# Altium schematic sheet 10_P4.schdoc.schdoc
size 309 x 223 mm; Symbol: A4_Schematic_0605; Device: A4_Schematic_0605; @Project Name: MDIO-Board_Rev_01(0124); @Page Count: 10; @Update Date: 2024-05-24; @Create Date: 2024-05-19; @Schematic Name: Schematic1; @Page No: 4; @Page Name: P4
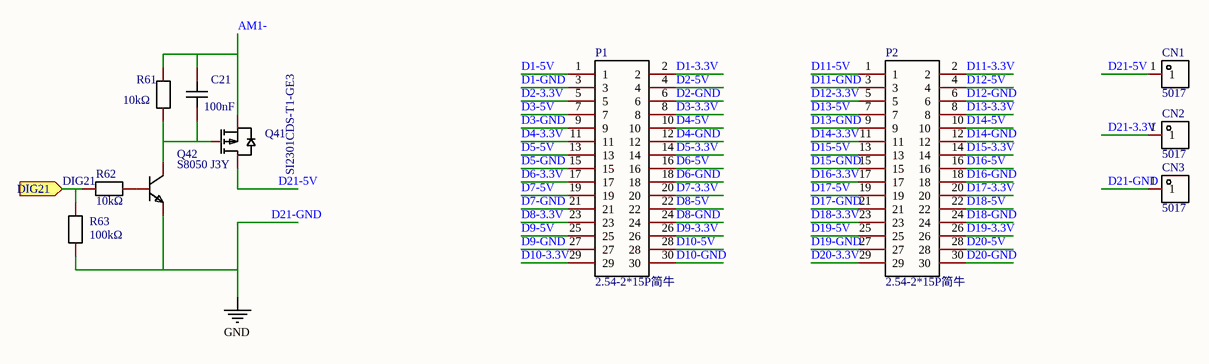
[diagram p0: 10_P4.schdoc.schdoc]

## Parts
C21  100nF  [C0603]
CN1  5017  [CONN-SMD_5017]
CN2  5017  [CONN-SMD_5017]
CN3  5017  [CONN-SMD_5017]
P1  2.54-2*15P简牛  [IDC-TH_30P-P2.54-V-R2-C15-S2.54]
P2  2.54-2*15P简牛  [IDC-TH_30P-P2.54-V-R2-C15-S2.54]
Q41  SI2301CDS-T1-GE3  [SOT-23-3_L3.0-W1.7-P0.95-LS2.9-BR]
Q42  S8050 J3Y  [SOT-23-3_L3.0-W1.7-P0.95-LS2.9-BR]
R61  10kΩ  [R0603]
R62  10kΩ  [R0603]
R63  100kΩ  [R0603]

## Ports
DIG21 (in)

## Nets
D21-GND: CN3.1 Q42.2(E) R63.1  [also labelled GND]
AM1-: C21.1 Q41.2(S) R61.2
D1-3.3V: P1.2
D1-5V: P1.1
D1-GND: P1.3
D2-3.3V: P1.5
D2-5V: P1.4
D2-GND: P1.6
D3-3.3V: P1.8
D3-5V: P1.7
D3-GND: P1.9
D4-3.3V: P1.11
D4-5V: P1.10
D4-GND: P1.12
D5-3.3V: P1.14
D5-5V: P1.13
D5-GND: P1.15
D6-3.3V: P1.17
D6-5V: P1.16
D6-GND: P1.18
D7-3.3V: P1.20
D7-5V: P1.19
D7-GND: P1.21
D8-3.3V: P1.23
D8-5V: P1.22
D8-GND: P1.24
D9-3.3V: P1.26
D9-5V: P1.25
D9-GND: P1.27
D10-3.3V: P1.29
D10-5V: P1.28
D10-GND: P1.30
D11-3.3V: P2.2
D11-5V: P2.1
D11-GND: P2.3
D12-3.3V: P2.5
D12-5V: P2.4
D12-GND: P2.6
D13-3.3V: P2.8
D13-5V: P2.7
D13-GND: P2.9
D14-3.3V: P2.11
D14-5V: P2.10
D14-GND: P2.12
D15-3.3V: P2.14
D15-5V: P2.13
D15-GND: P2.15
D16-3.3V: P2.17
D16-5V: P2.16
D16-GND: P2.18
D17-3.3V: P2.20
D17-5V: P2.19
D17-GND: P2.21
D18-3.3V: P2.23
D18-5V: P2.22
D18-GND: P2.24
D19-3.3V: P2.26
D19-5V: P2.25
D19-GND: P2.27
D20-3.3V: P2.29
D20-5V: P2.28
D20-GND: P2.30
D21-3.3V: CN2.1
D21-5V: CN1.1 Q41.3(D)
DIG21: R62.2 R63.2 ; port DIG21
NetC21_2: C21.2 Q41.1(G) Q42.3(C) R61.1
NetQ42_1: Q42.1(B) R62.1

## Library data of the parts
C21 = CC0603KRX7R9BB104: Manufacturer: YAGEO(国巨); Add into BOM: yes; Tolerance: ±10%; Description: Capacitance: Tolerance:±10% Tolerance:±10% Voltage Rated: Temperature Coefficient:
CN1-CN3 = 5017: Symbol: 5017_C9900015874; Add into BOM: yes
P1 P2 = 2.54-2*15P简牛: Manufacturer: BOOMELE(博穆精密); Symbol: 2X15P; Add into BOM: yes; Connector Type: 简牛座; Pitch: 2.54mm; Holder Type: Straight; Pin Number in each Row: 15; Description: Connector Type:简牛座 Pitch:2.54mm Structure:2x15P Holder Type:Straight Row Spacing:2.54mm Number of Rows:2 Pin Number in each Row:15 Contact Material:- Contact Plating:-
Q41 = SI2301CDS-T1-GE3: Manufacturer: VISHAY(威世); Add into BOM: yes; Type: 1个PChannel; Power Dissipation (Pd): ；; Drain Source On Resistance (RDS(on)@Vgs,Id): 112mΩ@4.5V,2.8A; Gate Threshold Voltage (Vgs(th)@Id): 1V@250uA; Total Gate Charge (Qg@Vgs): 10nC@4.5V; Input Capacitance (Ciss@Vds): 405pF@10V; Description: Type:1个PChannel Drain Source Voltage (Vdss): Continuous Drain Current (Id): Power Dissipation (Pd):； Drain Source On Resistance (RDS(on)@Vgs,Id):112mΩ@4.5V,2.8A Gate Threshold Voltage (Vgs(th)@Id):1V@250uA Total Gate Charge (Qg@Vgs):10nC@4.5V Input Capaci
Q42 = S8050 J3Y_C2146: Manufacturer: CJ(江苏长电/长晶); Symbol: S8050_C2146; Add into BOM: yes; DC Current Gain (hFE@Ic,Vce): 200@50mA,1V; Transition Frequency (fT): 150MHz; Collector Cut-Off Current (Icbo): 100nA; Collector-Emitter Saturation Voltage (VCE(sat)@Ic,Ib): 600mV@500mA,50mA; Description: Transistor Type: Collector Current (Ic): Collector-Emitter Breakdown Voltage (Vceo): Power Dissipation (Pd): DC Current Gain (hFE@Ic,Vce):200@50mA,1V DC Current Gain (hFE@Ic,Vce):200@50mA,1V Transition Frequency (fT):150MHz Collector Cut-Off Current (Icbo
R61 R62 = SCR0603J10K: Manufacturer: VO(翔胜); Add into BOM: yes; Tolerance: ±5%; Description: Type:Thick Film Resistors Resistance: Tolerance:±5% Tolerance:±5% Power(Watts): Overload Voltage (Max): Operating Temperature Range:-55℃~+155℃ Operating Temperature Range:-55℃~+155℃
R63 = SCR0603F100K: Manufacturer: VO(翔胜); Add into BOM: yes; Tolerance: ±1%; Description: Type:Thick Film Resistors Resistance: Tolerance:±1% Tolerance:±1% Power(Watts): Overload Voltage (Max): Operating Temperature Range:-55℃~+155℃ Operating Temperature Range:-55℃~+155℃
